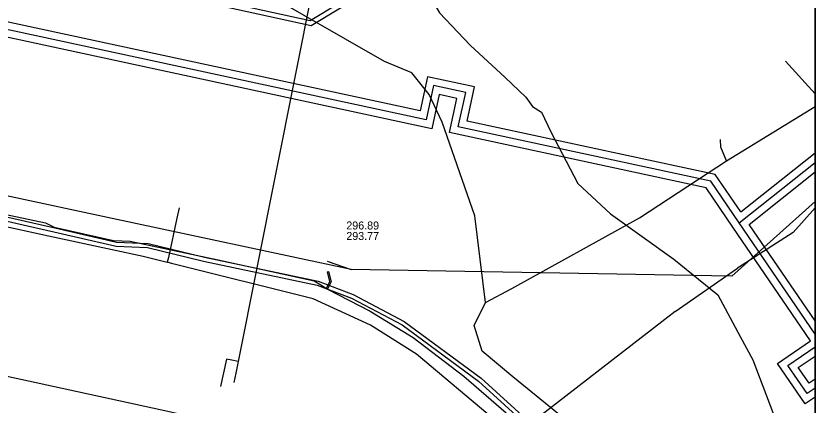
# Model space of a CAD drawing. Extents: x -598233 to -596890, y -1157848 to -1156431.
# Drawn here: x -596970.3 to -596890.5, y -1156733.5 to -1156694.6 of the extents above; entities that cross this region are included whole.
import ezdxf

# ---------------------------------------------------------------- set-up
doc = ezdxf.new("R2010")
doc.units = 0
for name, color, linetype in [('Vrstva 12', 7, 'Continuous'), ('Vrstva 13', 7, 'Continuous'), ('Vrstva 19', 7, 'Continuous'), ('Vrstva 25', 7, 'Continuous'), ('Vrstva 26', 7, 'Continuous'), ('Vrstva 37', 7, 'Continuous'), ('Vrstva 38', 7, 'Continuous'), ('Vrstva 44', 7, 'Continuous'), ('Vrstva 55', 7, 'Continuous'), ('Vrstva 58', 7, 'Continuous'), ('Vrstva 60', 7, 'Continuous'), ('Vrstva 9', 7, 'Continuous'), ('zajmove_uzemi', 7, 'Continuous')]:
    doc.layers.add(name, color=color, linetype=linetype)

msp = doc.modelspace()

# ---------------------------------------------------------------- linework, layer by layer
at = {"layer": 'Vrstva 12'}
for points in [[(-596928.9, -1156692.64), (-596927.99, -1156694.27), (-596924.9, -1156697.52), (-596921.41, -1156700.73), (-596919.34, -1156702.7), (-596918.68, -1156703.63), (-596917.78, -1156704.19), (-596916.85, -1156706.16), (-596914.16, -1156711.34), (-596910.89, -1156714.39), (-596904.56, -1156718.91), (-596900.16, -1156722.49), (-596897.928, -1156726.658)], [(-597002.46, -1156706.78), (-596998.34, -1156707.48), (-596988.48, -1156709.16), (-596987.49, -1156709.33), (-596982.56, -1156713.19), (-596967.05, -1156716.59), (-596960.69, -1156717.95), (-596957.58, -1156718.62), (-596955.18, -1156719.22)], [(-596953.99, -1156713.77), (-596954.22, -1156714.82), (-596955.07, -1156718.73), (-596955.18, -1156719.22)], [(-596890.462, -1156713.774), (-596892.66, -1156716.25), (-596898.209, -1156719.798)], [(-596954.61, -1156719.36), (-596955.18, -1156719.22)], [(-596922.52, -1156734.93), (-596930.29, -1156728.41), (-596934.88, -1156725.51), (-596940.61, -1156722.86), (-596954.61, -1156719.36)], [(-596904.435, -1156724.135), (-596898.209, -1156719.798)], [(-596904.435, -1156724.135), (-596920.53, -1156736.62)], [(-596897.928, -1156726.658), (-596896.69, -1156728.97), (-596893.96, -1156736.18), (-596893.86, -1156738.38), (-596893.97, -1156743.17), (-596893.95, -1156745.94), (-596893.43, -1156746.93), (-596893.72, -1156747.64)]]:
    msp.add_lwpolyline(points, dxfattribs=at)
at = {"layer": 'Vrstva 13'}
for points in [[(-596940.617, -1156691.482), (-596948.106, -1156729.131), (-596948.339, -1156730.315), (-596948.53, -1156731.238)], [(-596948.106, -1156729.131), (-596948.723, -1156729.01), (-596949.265, -1156728.895), (-596949.846, -1156731.643)]]:
    msp.add_lwpolyline(points, dxfattribs=at)
at = {"layer": 'Vrstva 19'}
msp.add_lwpolyline([(-597039.338, -1156716.156), (-597017.63, -1156720.79), (-597000.4, -1156724.25), (-596966.43, -1156731.65), (-596955.13, -1156734.11), (-596943.94, -1156736.68), (-596938.65, -1156737.65), (-596912.06, -1156762.18), (-596900.41, -1156772.14), (-596895.82, -1156776.43)], dxfattribs=at)
at = {"layer": 'Vrstva 25'}
for p, q in [((-596944.163, -1156701.776), (-596974.443, -1156695.246)), ((-596929.328, -1156704.975), (-596944.163, -1156701.776)), ((-596898.039, -1156715.276), (-596890.462, -1156709.227)), ((-596890.462, -1156726.404), (-596898.039, -1156715.276))]:
    msp.add_line(p, q, dxfattribs=at)
for points in [[(-596926.103, -1156705.671), (-596925.365, -1156702.25), (-596928.59, -1156701.554), (-596929.328, -1156704.975)], [(-596898.039, -1156715.276), (-596900.875, -1156711.111), (-596926.103, -1156705.671)], [(-596890.462, -1156731.802), (-596891.258, -1156732.344), (-596893.172, -1156729.533), (-596890.462, -1156727.689)]]:
    msp.add_lwpolyline(points, dxfattribs=at)
at = {"layer": 'Vrstva 26'}
for p, q in [((-596929.903, -1156704.084), (-596973.551, -1156694.671)), ((-596928.753, -1156705.866), (-596975.335, -1156695.821)), ((-596897.875, -1156714.185), (-596890.462, -1156708.268)), ((-596897.028, -1156715.428), (-596890.462, -1156710.186)), ((-596890.462, -1156725.072), (-596897.028, -1156715.428)), ((-596890.907, -1156727.084), (-596898.659, -1156715.698))]:
    msp.add_line(p, q, dxfattribs=at)
for points in [[(-596925.212, -1156705.096), (-596924.474, -1156701.675), (-596929.165, -1156700.663), (-596929.903, -1156704.084)], [(-596926.994, -1156706.246), (-596926.256, -1156702.825), (-596928.015, -1156702.445), (-596928.753, -1156705.866)], [(-596897.875, -1156714.185), (-596900.424, -1156710.441), (-596925.212, -1156705.096)], [(-596898.659, -1156715.698), (-596901.326, -1156711.781), (-596926.994, -1156706.246)], [(-596890.462, -1156732.71), (-596891.456, -1156733.386), (-596894.214, -1156729.335), (-596890.907, -1156727.084)], [(-596890.462, -1156730.895), (-596891.06, -1156731.302), (-596892.13, -1156729.731), (-596890.462, -1156728.596)]]:
    msp.add_lwpolyline(points, dxfattribs=at)
at = {"layer": 'Vrstva 37'}
msp.add_lwpolyline([(-596994.927, -1156683.194), (-596990.833, -1156684.091), (-596940.89, -1156695.028), (-596921.559, -1156683.329)], dxfattribs=at)
at = {"layer": 'Vrstva 38'}
msp.add_lwpolyline([(-596921.3, -1156683.757), (-596940.802, -1156695.559), (-596995.034, -1156683.682)], dxfattribs=at)
at = {"layer": 'Vrstva 44'}
for points in [[(-597005.585, -1156671.636), (-597008.271, -1156671.039), (-597008.311, -1156673.603), (-597007.308, -1156676.385), (-597005.397, -1156678.063), (-597000.258, -1156679.068), (-596991.607, -1156680.817), (-596982.386, -1156682.908), (-596981.392, -1156684.271), (-596981.538, -1156686.007), (-596985.188, -1156704.248), (-596984.686, -1156709.143), (-596983.376, -1156711.962), (-596981.851, -1156713.132), (-596978.379, -1156713.471), (-596966.509, -1156716.176), (-596960.295, -1156717.6), (-596957.149, -1156717.728), (-596951.564, -1156719.115), (-596940.201, -1156721.51), (-596936.768, -1156722.799), (-596931.708, -1156725.472), (-596924.08, -1156731.126), (-596910.934, -1156743.097)], [(-597005.652, -1156671.884), (-597007.842, -1156671.377), (-597007.91, -1156673.536), (-597006.967, -1156676.152), (-597005.214, -1156677.691), (-597000.18, -1156678.676), (-596991.523, -1156680.426), (-596982.151, -1156682.551), (-596980.981, -1156684.156), (-596981.141, -1156686.063), (-596984.784, -1156704.267), (-596984.295, -1156709.035), (-596983.055, -1156711.704), (-596981.698, -1156712.745), (-596978.315, -1156713.075), (-596966.42, -1156715.786), (-596960.242, -1156717.202), (-596957.092, -1156717.33), (-596951.475, -1156718.725), (-596940.089, -1156721.125), (-596936.604, -1156722.433), (-596931.494, -1156725.133), (-596923.826, -1156730.817), (-596910.736, -1156742.737)]]:
    msp.add_lwpolyline(points, dxfattribs=at)
at = {"layer": 'Vrstva 55'}
msp.add_lwpolyline([(-596976.66, -1156713.3), (-596967.35, -1156715.29), (-596966.49, -1156715.7), (-596960.54, -1156717.05), (-596958.9, -1156717.1), (-596950.09, -1156718.96), (-596940.51, -1156721.09), (-596939.68, -1156721.584), (-596939.262, -1156721.839), (-596938.933, -1156721.154), (-596939.178, -1156720.174), (-596939.062, -1156720.145), (-596938.807, -1156721.166), (-596939.157, -1156721.898), (-596934.91, -1156724.11), (-596930.62, -1156726.76), (-596925.55, -1156730.61), (-596921.305, -1156734.291)], dxfattribs=at)
at = {"layer": 'Vrstva 58'}
msp.add_line((-596899.3, -1156709.08), (-596890.462, -1156703.636), dxfattribs=at)
for points in [[(-596923.37, -1156723.25), (-596924.46, -1156714.56), (-596927.7, -1156705.2), (-596929.01, -1156702.44), (-596930.76, -1156700.27), (-596933.49, -1156699.15), (-596945.39, -1156692.27), (-596953.96, -1156689.49)], [(-596899.3, -1156709.08), (-596899.87, -1156707.72), (-596899.905, -1156706.95)], [(-596923.37, -1156723.25), (-596920.75, -1156721.85), (-596907.99, -1156714.78), (-596899.3, -1156709.08)], [(-596890.462, -1156756.382), (-596902.63, -1156744), (-596903.6, -1156743.43), (-596904.53, -1156744.11), (-596906.89, -1156742.88), (-596914.18, -1156735.94), (-596920.66, -1156730.68), (-596923.72, -1156728.12), (-596924.53, -1156725.54), (-596923.37, -1156723.25)]]:
    msp.add_lwpolyline(points, dxfattribs=at)
at = {"layer": 'Vrstva 60'}
msp.add_lwpolyline([(-596890.462, -1157848.461), (-596890.462, -1156430.856)], dxfattribs=at)
at = {"layer": 'Vrstva 9'}
for p, q in [((-596893.4, -1156699.09), (-596890.462, -1156702.38)), ((-596890.462, -1156713.132), (-596898.78, -1156720.62)), ((-596939.189, -1156719.107), (-596936.812, -1156719.926))]:
    msp.add_line(p, q, dxfattribs=at)
for points in [[(-596936.813, -1156719.926), (-596961.147, -1156714.73), (-596961.148, -1156714.73), (-596980.423, -1156710.615), (-596980.804, -1156710.534), (-596980.805, -1156710.533), (-596982.507, -1156710.17)], [(-596898.78, -1156720.62), (-596900.8, -1156720.583), (-596936.813, -1156719.926)]]:
    msp.add_lwpolyline(points, dxfattribs=at)
at = {"layer": 'zajmove_uzemi'}
msp.add_lwpolyline([(-598232.89, -1156430.856), (-596890.462, -1156430.856), (-596890.462, -1157848.461), (-598232.89, -1157848.461)], close=True, dxfattribs=at)

# ---------------------------------------------------------------- texts
at = {"layer": 'Vrstva 12'}
for s, p in [('296.89', (-596937.291, -1156715.94)), ('293.77', (-596937.291, -1156716.99))]:
    msp.add_text(s, height=0.8, dxfattribs=at).set_placement(p)

doc.saveas('drawing.dxf')
